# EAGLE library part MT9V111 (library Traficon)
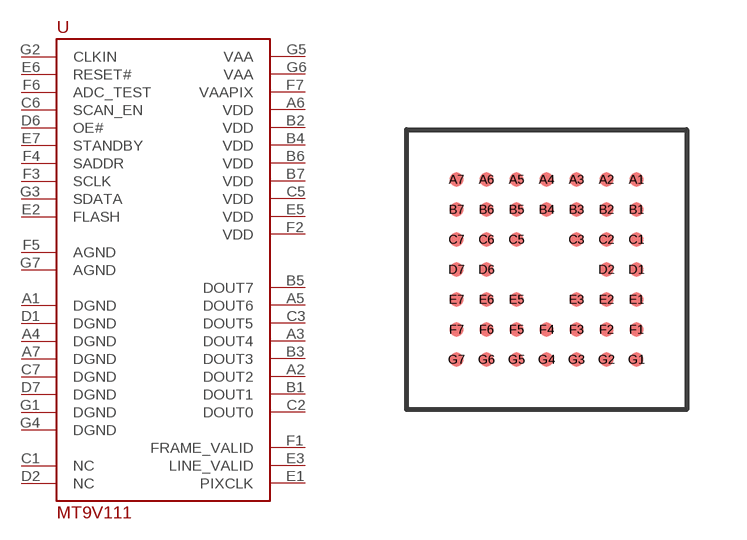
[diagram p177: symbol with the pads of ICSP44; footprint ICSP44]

Designator prefix U

## MT9V111  [ICSP44]
A1  DGND  pwr
A2  DOUT2  out
A3  DOUT4  out
A4  DGND  pwr
A5  DOUT6  out
A6  VDD  pwr
A7  DGND  pwr
B1  DOUT1  out
B2  VDD  pwr
B3  DOUT3  out
B4  VDD  pwr
B5  DOUT7  out
B6  VDD  pwr
B7  VDD  pwr
C1  NC  nc
C2  DOUT0  out
C3  DOUT5  out
C5  VDD  pwr
C6  SCAN_EN  in
C7  DGND  pwr
D1  DGND  pwr
D2  NC  nc
D6  OE#  in
D7  DGND  pwr
E1  PIXCLK  out
E2  FLASH  out
E3  LINE_VALID  out
E5  VDD  pwr
E6  RESET#  in
E7  STANDBY  in
F1  FRAME_VALID  out
F2  VDD  pwr
F3  SCLK  in
F4  SADDR  in
F5  AGND  pwr
F6  ADC_TEST  in
F7  VAAPIX  pwr
G1  DGND  pwr
G2  CLKIN  in
G3  SDATA
G4  DGND  pwr
G5  VAA  pwr
G6  VAA  pwr
G7  AGND  pwr

## Footprint ICSP44 (pad centres in mm)
smd 0.35 x 0.35: A1 2.25,2.25; A2 1.5,2.25; A3 0.75,2.25; A4 0,2.25; A5 -0.75,2.25; A6 -1.5,2.25; A7 -2.25,2.25; B1 2.25,1.5; B2 1.5,1.5; B3 0.75,1.5; B4 0,1.5; B5 -0.75,1.5; B6 -1.5,1.5; B7 -2.25,1.5; C1 2.25,0.75; C2 1.5,0.75; C3 0.75,0.75; C5 -0.75,0.75; C6 -1.5,0.75; C7 -2.25,0.75; D1 2.25,0; D2 1.5,0; D6 -1.5,0; D7 -2.25,0; E1 2.25,-0.75; E2 1.5,-0.75; E3 0.75,-0.75; E5 -0.75,-0.75; E6 -1.5,-0.75; E7 -2.25,-0.75; F1 2.25,-1.5; F2 1.5,-1.5; F3 0.75,-1.5; F4 0,-1.5; F5 -0.75,-1.5; F6 -1.5,-1.5; F7 -2.25,-1.5; G1 2.25,-2.25; G2 1.5,-2.25; G3 0.75,-2.25; G4 0,-2.25; G5 -0.75,-2.25; G6 -1.5,-2.25; G7 -2.25,-2.25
